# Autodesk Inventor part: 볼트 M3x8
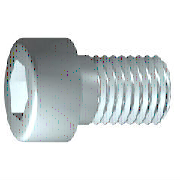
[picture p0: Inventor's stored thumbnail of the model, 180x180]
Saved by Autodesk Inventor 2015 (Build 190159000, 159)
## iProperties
IsCustomPart: 0
Created: 2012-02
Part Number: 볼트 M3x8
Material: 강철, 연강
Description: 6각머리 태핑 나사
Document SubType Name: Modeling
Standard: KS B 1003
Designer: mduedu
Standards Organization: KS
Language: ko-KR
Size Designation: M 3 x 8
Categories: <MemberInstance><Categories><Category DisplayName="조임쇠" InternalName="e4da775c-781d-43d5-af7c-5136215cf5a6" Mnemonic="FSTN"><Category DisplayName="볼트" InternalN
Density: 7.85 g/cm^3
Appearance: 강철
Mass: 0.928661 g
Surface Area: 1.83001 cm^2
Volume: 0.118301 cm^3
Author: mduedu
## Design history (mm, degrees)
sketch "스케치1"
  geometry: L1 (-0.867, 0)-(8, 0); L2 (8, 0)-(8, 1.5); L3 (8, 1.5)-(1.25, 1.5); L4 (1.25, 1.5)-(0.943, 1.5); L5 (0.943, 1.5)-(0, 1.5); L6 (0, 1.5)-(0, 2.75); L7 (0, 2.75)-(-3, 2.75); L8 (-3, 2.75)-(-3, 1.443); L9 (-3, 1.443)-(-1.7, 1.443); L10 (-1.7, 1.443)-(-0.867, 0); L11 (-5.2, 0)-(10.2, 0) reference; L12 (0, -0.55)-(0, 3.3) reference; L13 (1.25, 1.5)-(0, 1.5)
  constraints: 22 end point, 6 parallel, 2 collinear, 2 perpendicular, 1 horizontal, 1 point on line
  dimensions: "d1" = 6.75 distance from line of L3.end L2 (= GEL); "d2" = 0.30683 distance of L4.end L3.end (computed from GAL); "d3" = 3 distance between parallel lines of L8 L6 (= KOH); "d4" = 1.3 distance of L8.end L9.end (= INTI); "d5" = 60 deg angle of L10 L1; "d6" = 3 diameter of L3 L1 (= GD); "d7" = 3 diameter of L5 L1 (= BDM); "d8" = 2.88675 diameter of L9 L1 (= 1.1547 x SW); "d9" = 5.5 diameter of L7 L1 (= KOD); "d26" = 8 distance between parallel lines of L12 L2 (= NLG)
revolve "본체" sketch "스케치1" stored, may be unused: angle "d10" = 90 deg
sketch "스케치2"
  geometry: L1 (0, -3.85)-(0, 3.85) reference; L2 (-3.85, 0)-(3.85, 0) reference; L3 (1.443, 0)-(0.722, -1.25); L4 (0.722, -1.25)-(-0.722, -1.25); L5 (-0.722, -1.25)-(-1.443, 0); L6 (-1.443, 0)-(-0.722, 1.25); L7 (-0.722, 1.25)-(0.722, 1.25); L8 (0.722, 1.25)-(1.443, 0); 2 further points
  constraints: 12 end point, 1 coincident, 1 horizontal alignment, 1 point on line, 12 other
extrude "슬롯" join sketch "스케치2" stored distance "d11" = 10; taper "d12" = 0 deg
workplane "Work Plane1"
fillet "Fillet2" dims "d30" = 0.1 (= R)
body "Solid1"
fillet "모깎기1" dims "d17" = 0.3 (= RR)
feature "스레드" dims "d13" = 6.75 (= GEL), "d14" = 0
chamfer "모따기1" distance "d15" = 0.30673 (= -0.5 x SPD + 0.5 x GD); stored, may be unused: second distance "d16" = 0.30673 (= GUL), angle "d27" = 45 deg
other parameters: "GD" = 3 (= NND) [user parameter; used in 2 equation terms], "NLG" = 8 [user parameter; used in 1 equation term], "GEL" = 6.75 [user parameter; used in 2 equation terms], "KOD" = 5.5 [user parameter; used in 1 equation term], "KOH" = 3 [user parameter; used in 1 equation term], "INTI" = 1.3 [user parameter; used in 1 equation term], "GAL" = 0.30673 (= 0.61345 x PTC) [user parameter; used in 1 equation term], "GUL" = 0.30673 (= 0.61345 x PTC) [user parameter; used in 1 equation term], "BDM" = 3 (= NND) [user parameter; used in 1 equation term], "SW" = 2.5 [user parameter; used in 2 equation terms], "RR" = 0.3 [user parameter; used in 1 equation term], "SPD" = 2.38655 (= NND - 1.2269 x PTC) [user parameter; used in 1 equation term], "d19" = 0, "d28" = 0, "d29" = 0, "R" = 0.1 [user parameter; used in 1 equation term], "PHH" = 0.1 [user parameter], "GD1" = 2.38655 (= THREADDIA - 1.2269 x PTC) [user parameter], "THREADDIA" = 3 [user parameter; used in 1 equation term], "FAWI" = 45 deg [user parameter], "PTC" = 0.5 [user parameter; used in 5 equation terms], "NND" = 3 [user parameter; used in 3 equation terms], "TOA" = 30 deg [user parameter], "E0" = 2.8875 (= 1.155 x SW) [user parameter]
